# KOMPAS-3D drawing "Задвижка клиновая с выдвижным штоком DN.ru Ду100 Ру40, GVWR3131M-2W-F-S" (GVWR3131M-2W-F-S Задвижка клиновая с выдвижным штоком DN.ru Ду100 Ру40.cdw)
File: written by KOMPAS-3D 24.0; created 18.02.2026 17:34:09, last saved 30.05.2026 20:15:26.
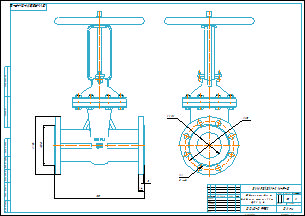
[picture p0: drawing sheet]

Document properties: art: D040-09239; Автор: R2D2; Форматы листов документа: A2; Полное имя файла: GVWR3131M-2W-F-S Задвижка клиновая с выдвижным штоком DN.ru Ду100 Ру40.m3d; Масса: 39; Наименование: Задвижка клиновая с выдвижным штоком DN.ru Ду100 Ру40; Количество листов документа: 1; Примечание: D040-09952

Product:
- Component [detail]: Деталь2  | qty 1  | pos. 1  | Масса: 4.922929; Автор: R2D2; additional columns: Типовые; source file: ..\Деталь2 Деталь2.m3d
- Component [detail]: ANSI B18.2.4.2M - M5x0,8 - 8  | designation ANSI B18.2.4.2M - M5x0,8  | qty 2  | pos. 2  | Комментарий: Типы метрических   шестигранных гаек   2; Автор: R2D2; additional columns: Сталь, мягкая; source file: ..\ANSI B18.2.4.2M - M5x0,8 ANSI B18.2.4.2M - M5x0,8 - 8.m3d
- Component [detail]: Деталь1  | qty 1  | pos. 3  | additional columns: Типовые; source file: ..\2.m3d
- Component [detail]: Деталь1  | qty 1  | pos. 3  | Автор: R2D2; additional columns: Типовые; source file: ..\3.m3d
- Component [detail]: Деталь1  | qty 2  | pos. 3  | Автор: R2D2; additional columns: Типовые; source file: ..\1.m3d
- Component [standard]: Болт М12-6gx50.88.45Г.019 ГОСТ 7798-70  | qty 8  | Материал: Сталь 45Г (density 7850 kg/m3); Масса: 0.06053; Раздел спецификации: Стандартные изделия; Рассекать на разрезах: no; additional columns: BOSimple***Material:39848d99-529e-4aa2-825c-393daa009d15
- Component [standard]: Гайка М12-6H ГОСТ 5915-70  | qty 24  | Масса: 0.0184; Раздел спецификации: Стандартные изделия; Рассекать на разрезах: no
- Part/product: Задвижка клиновая с выдвижным штоком DN.ru Ду100 Ру40  | designation GVWR3131M-2W-F-S
    Масса: 39
    Раздел спецификации: Прочие изделия
    Примечание: D040-09952

Views: Вид 1, Справа
Referenced files in E:\Работа\Зайцев\GVWR3131M-2W-F-S Задвижка клиновая с выдвижным штоком DN.ru Ду50-200 Ру63\DN100\: GVWR3131M-2W-F-S Задвижка клиновая с выдвижным штоком DN.ru Ду100 Ру63.m3d
Referenced files in E:\Работа\Зайцев\GVWR3131M-2W-F-S Задвижка клиновая с выдвижным штоком DN.ru Ду50-100 Ру40\исходные материалы\DN100\DN100\: GVWR3131M-2W-F-S Задвижка клиновая с выдвижным штоком DN.ru Ду100 Ру40.m3d
Referenced files in E:\Работа\Зайцев\Для компаса\: чертеж DN.ru А3.cdt
Referenced files in E:\Работа\Зайцев\GVWR3131M-2W-F-S Задвижка клиновая с выдвижным штоком DN.ru Ду50-100 Ру40\исходные материалы\DN100\: Деталь2 Деталь2.m3d, ANSI B18.2.4.2M - M5x0,8 ANSI B18.2.4.2M - M5x0,8 - 8.m3d, 2.m3d, 3.m3d, 1.m3d
Referenced files in C:\Program Files\ASCON\KOMPAS-3D v24\Libs\PolynomLib\DATA\vault\Methods\Kompas\3D\: PLib_Bolt_1_900.m3d, PLib_Nut_OST92_900.m3d
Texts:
  GVWR3131M-2W-F-S
  чертеж DN.ru А3.cdt
  Задвижка клиновая с
  выдвижным штоком DN.ru
  Ду100 Ру40
  Твердое тело1
  Деталь2
  Деталь2 Деталь2
  Solid1
  ANSI B18.2.4.2M - M5x0,8 - 8
  ANSI B18.2.4.2M - M5x0,8
  ANSI B18.2.4.2M - M5x0,8 ANSI B18.2.4.2M - M5x0,8 - 8
  Деталь1
  Деталь1 Деталь1
  Болт М12-6gx50.88.45Г.019 ГОСТ 7798-70
  Гайка М12-6H ГОСТ 5915-70
  Задвижка клиновая с выдвижным штоком DN.ru Ду100 Ру40
  GVWR3131M-2W-F-S Задвижка клиновая с выдвижным штоком DN.ru Ду100 Ру40
Dimensions and other numbers on the sheet: 0; 3; 2; 4; 350; 230; 158; 24; 1:2; 1; 39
